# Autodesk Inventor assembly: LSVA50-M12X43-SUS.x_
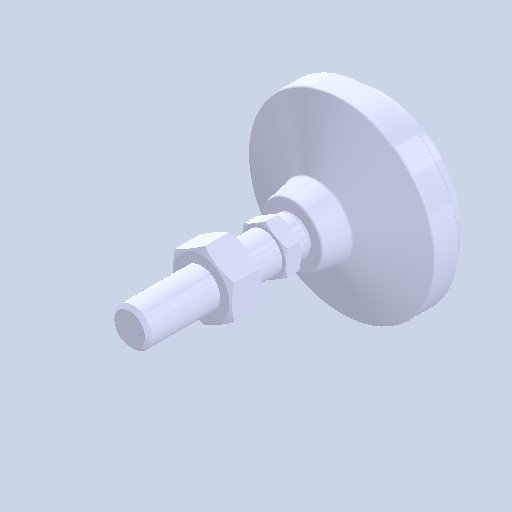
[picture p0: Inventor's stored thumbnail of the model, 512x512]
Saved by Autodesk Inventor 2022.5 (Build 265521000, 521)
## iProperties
Created: 2024-08
Part Number: LSVA50-M12X43-SUS.x_
Document SubType Name: Assembly
Designer: ImaoCorp
Author: ImaoCorp
Sending System: SOLIDWORKS 2022-2022290
MC: AMD64
MC_MODEL: Intel64 Family 6 Model 60 Stepping 3, GenuineIntel
OS: Windows_NT
FRU: Parasolid Version 33.1, build 260,  4-25-2022
FORMAT: text
GUISE: transmit
KEY: FILELSVA50-M12X43-SUS.x_t
DATE: Fri Aug 23 16:08:20 2024
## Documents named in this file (4)
- X:\14_SW2022-Inv2022\06_2024-10新製品(SME)\ELS_データ\l\lsva50-m12x43-sus\LSVA50-M12X43-SUS.x_.iam
- X:\14_SW2022-Inv2022\06_2024-10新製品(SME)\ELS_データ\l\lsva50-m12x43-sus\LSVA50-M12X43-SUS_01.ipt
- X:\14_SW2022-Inv2022\06_2024-10新製品(SME)\ELS_データ\l\lsva50-m12x43-sus\LSVA50-M12X43-SUS_02.ipt
- X:\14_SW2022-Inv2022\06_2024-10新製品(SME)\ELS_データ\l\lsva50-m12x43-sus\LSVA50-M12X43-SUS_03.ipt
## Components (3 placed, 3 different names)
1. LSVA50-M12X43-SUS_01
2. LSVA50-M12X43-SUS_02
3. LSVA50-M12X43-SUS_03
